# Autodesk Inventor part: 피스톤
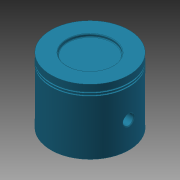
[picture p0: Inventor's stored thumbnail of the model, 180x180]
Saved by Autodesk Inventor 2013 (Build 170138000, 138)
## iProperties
Created: 2016-11
Part Number: 피스톤
Material: 강철, 탄소
Document SubType Name: Modeling
Designer: mduedu
Density: 7.87 g/cm^3
Mass: 410.115 g
Surface Area: 237.491 cm^2
Volume: 52.1112 cm^3
Author: mduedu
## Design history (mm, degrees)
sketch "스케치1"
  geometry: C1 r 30 at (0, 0); 1 further point
  constraints: 1 centre point, 1 coincident
  dimensions: "d0" = 60 diameter of C1
extrude "돌출1" new body sketch "스케치1" distance "d1" = 50; taper "d2" = 0 deg
sketch "스케치2"
  geometry: C1 r 28 at (0, 0); 1 further point
  constraints: 1 centre point, 1 coincident
  dimensions: "d3" = 56 diameter of C1
extrude "돌출2" cut sketch "스케치2" distance "d4" = 45; taper "d5" = 0 deg
sketch "스케치3"
  geometry: L1 (30, 0)-(30, 50) reference; L2 (30, 45)-(29, 45); L3 (29, 45)-(29, 44); L4 (29, 44)-(30, 44); L5 (30, 44)-(30, 45); L6 (30, 43)-(29, 43); L7 (29, 43)-(29, 42); L8 (29, 42)-(30, 42); L9 (30, 42)-(30, 43); L10 (30, 50)-(-30, 50) reference; L11 (0, 50)-(0, 0)
  constraints: 18 end point, 4 parallel, 3 equal length, 3 perpendicular, 2 horizontal, 2 point on line, 1 midpoint
  dimensions: "d6" = 1 distance of L2.start L2.end; "d8" = 5 distance between parallel lines of L10 L2; "d9" = 1 distance between parallel lines of L6 L4
revolve "회전1" sketch "스케치3" stored, may be unused: angle "d10" = 90 deg
node "작업 평면1"
sketch "스케치4"
  geometry: L1 (0, -22.978)-(45, -22.978) reference; L2 (45, -22.978)-(45, 22.978) reference; L3 (45, 22.978)-(0, 22.978) reference; L4 (0, 22.978)-(0, 25.377) reference; L5 (0, 25.377)-(42, 25.377) reference; L6 (42, 25.377)-(42, 24.187) reference; L7 (42, 24.187)-(43, 24.187) reference; L8 (43, 24.187)-(43, 25.377) reference; L9 (43, 25.377)-(44, 25.377) reference; L10 (44, 25.377)-(44, 24.187) reference; L11 (44, 24.187)-(45, 24.187) reference; L12 (45, 24.187)-(45, 25.377) reference; L13 (45, 25.377)-(50, 25.377) reference; L14 (50, 25.377)-(50, -25.377) reference; L15 (50, -25.377)-(45, -25.377) reference; L16 (45, -25.377)-(45, -24.187) reference; L17 (45, -24.187)-(44, -24.187) reference; L18 (44, -24.187)-(44, -25.377) reference; L19 (44, -25.377)-(43, -25.377) reference; L20 (43, -25.377)-(43, -24.187) reference; L21 (43, -24.187)-(42, -24.187) reference; L22 (42, -24.187)-(42, -25.377) reference; L23 (42, -25.377)-(0, -25.377) reference; L24 (0, -25.377)-(0, -22.978) reference; L25 (12.5, 22.978)-(45, 22.978); L26 (45, 22.978)-(45, -22.978); L27 (45, -22.978)-(12.5, -22.978); L28 (12.5, -22.978)-(12.5, 22.978); C1 r 7.5 at (20, 0); C2 r 4 at (20, 0); 1 further point
  constraints: 8 end point, 2 centre point, 2 parallel, 1 coincident, 1 horizontal, 1 horizontal alignment, 1 perpendicular, 1 point on line, 1 tangent
  dimensions: "d12" = 15 diameter of C1; "d13" = 8 diameter of C2; "d14" = 20 distance of point (0, 0) C1.centre
  node "절단 모서리 투영1"
extrude "돌출3" join sketch "스케치4" stored distance "d15" = 11.75; taper "d16" = 0 deg
extrude "돌출4" cut sketch "스케치4" stored distance "d17" = 72; taper "d18" = 0 deg
fillet "모깎기2" dims "d20" = 3
chamfer "모따기1" distance "d21" = 0.5; stored, may be unused: second distance "d22" = 2, angle "d23" = 45 deg
chamfer "모따기2" distance "d24" = 0.5; stored, may be unused: second distance "d25" = 2, angle "d26" = 45 deg
sketch "스케치5"
  geometry: C1 r 17.5 at (0, 0); 1 further point
  constraints: 1 centre point, 1 coincident
  dimensions: "d27" = 35 diameter of C1
extrude "돌출5" cut sketch "스케치5" distance "d28" = 2; taper "d29" = 0 deg
fillet "모깎기3" dims "d30" = 0.5
node "솔리드1"
mirror "대칭1"
other parameters: "d11" = -16
